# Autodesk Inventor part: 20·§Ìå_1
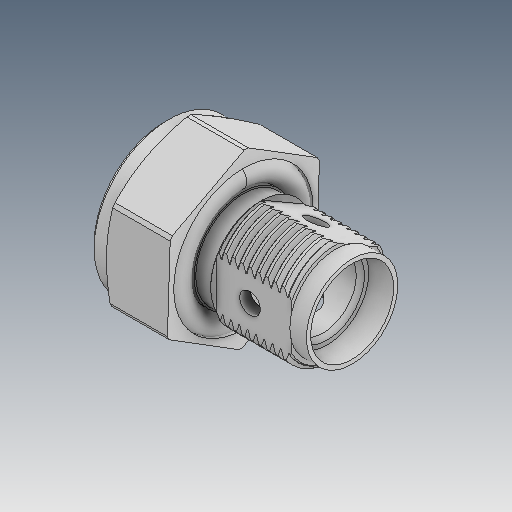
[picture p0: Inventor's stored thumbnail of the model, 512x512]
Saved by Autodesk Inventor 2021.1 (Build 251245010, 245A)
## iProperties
Created: 2019-12
Part Number: 20·§Ìå_1
Material: Ogólny
Document SubType Name: Modeling
Designer: user
Density: 1 g/cm^3
Appearance: Domyślna
Author: user
Revision Number: ÈÎºÎ
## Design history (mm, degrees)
feature "ÊäÈë1"
feature "ÊäÈë2"
node "Bryła1"
node "Bryła2"
